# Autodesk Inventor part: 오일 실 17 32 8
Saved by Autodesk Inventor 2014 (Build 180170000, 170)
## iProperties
Created: 2026-07
Part Number: 오일 실 17 32 8
Material: 일반
Document SubType Name: Modeling
Designer: dg
Density: 1 g/cm^3
Appearance: 기본값
Author: dg
Author: jhkim
Description: 오일-실
Creation Date: 2026-07-02
Sending System: Autodesk Inventor 2027
Preprocessor: ST-DEVELOPER v20.1
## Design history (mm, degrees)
node "오일 실 17 32 81"
body "Solid1"
node "기준1"
